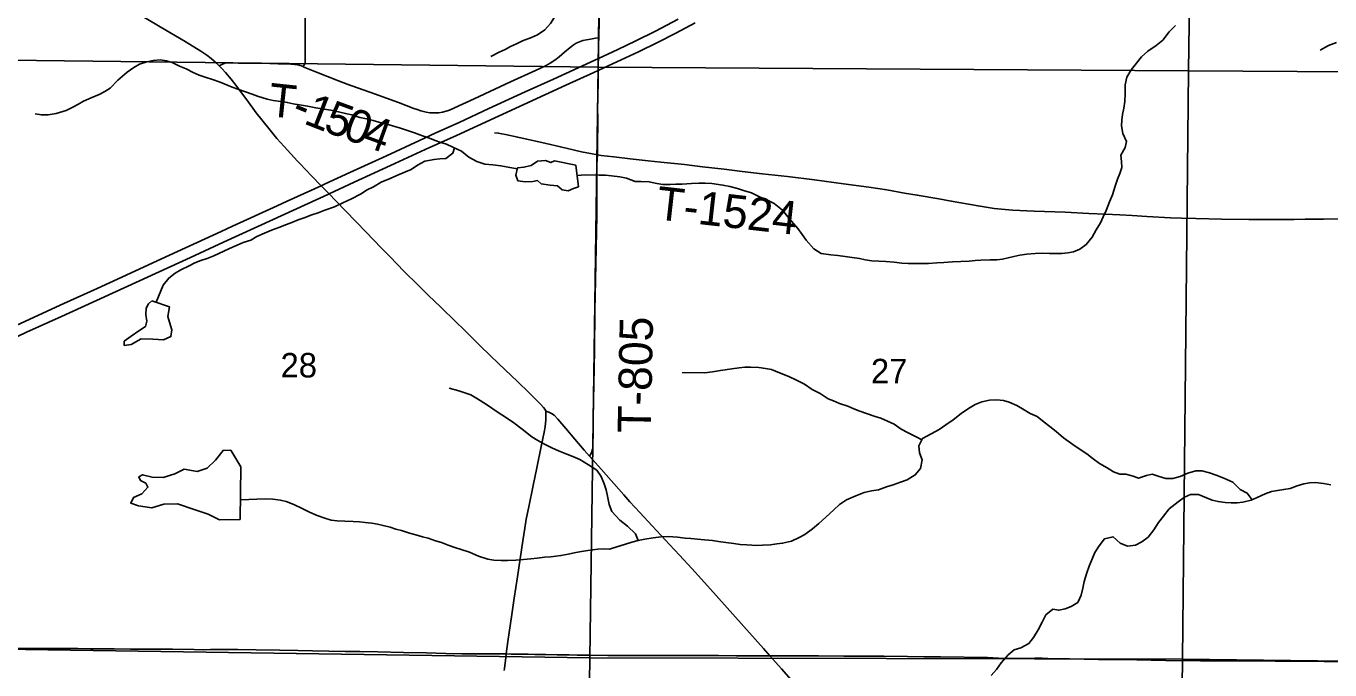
# Model space of a CAD drawing. Extents: x 1874609 to 2204689, y 815661 to 1281160.
# Drawn here: x 2024389 to 2036147, y 1030217 to 1036022 of the extents above; entities that cross this region are included whole.
import ezdxf

# ---------------------------------------------------------------- set-up
doc = ezdxf.new("R2010")
doc.units = 0
for name, color, linetype in [('GM_X_County_Road', 7, 'Continuous'), ('GM_X_Interstate_Route', 7, 'Continuous'), ('GM_X_Minor_Lake', 7, 'Continuous'), ('GM_X_Minor_River', 7, 'Continuous'), ('GM_X_Section', 7, 'Continuous'), ('GM_X_Section_Text', 7, 'Continuous'), ('GM_X_State_Route', 7, 'Continuous'), ('GM_X_Township_Road', 7, 'Continuous'), ('GM_X_Township_Road_Text', 7, 'Continuous')]:
    doc.layers.add(name, color=color, linetype=linetype)

msp = doc.modelspace()

# ---------------------------------------------------------------- linework, layer by layer
at = {"layer": 'GM_X_County_Road'}
for points in [[(2029076, 1032550), (2029103, 1032541), (2029128, 1032529), (2029150, 1032513), (2029183, 1032477), (2029256, 1032393), (2029337, 1032299), (2029422, 1032200), (2029471, 1032145)], [(2029471, 1032145), (2029574, 1032028), (2029781, 1031795), (2029835, 1031733), (2029923, 1031636), (2030034, 1031516), (2030112, 1031431), (2030190, 1031348), (2030281, 1031252), (2030392, 1031132), (2030481, 1031035), (2030612, 1030888), (2030788, 1030694), (2031038, 1030411), (2031096, 1030345)], [(2024315, 1030412), (2024447, 1030410), (2024578, 1030410), (2024643, 1030409), (2024725, 1030410), (2024790, 1030410), (2024856, 1030409), (2024971, 1030408), (2025085, 1030407), (2025184, 1030407), (2025331, 1030405), (2025479, 1030404), (2025709, 1030403), (2025906, 1030400), (2025987, 1030399), (2026053, 1030400), (2026299, 1030400), (2026463, 1030398), (2026676, 1030395), (2026840, 1030392), (2026971, 1030390), (2027266, 1030384), (2027398, 1030382), (2027562, 1030379), (2027793, 1030374), (2028000, 1030370), (2028175, 1030366), (2028320, 1030363), (2028381, 1030362), (2028430, 1030363), (2028451, 1030363), (2028502, 1030363), (2028560, 1030362), (2028641, 1030361), (2028684, 1030361), (2028719, 1030361)], [(2031096, 1030345), (2031200, 1030226), (2031439, 1029956), (2031537, 1029846), (2031701, 1029663), (2031790, 1029566), (2031791, 1029565)]]:
    msp.add_lwpolyline(points, dxfattribs=at)
at = {"layer": 'GM_X_Interstate_Route'}
for points in [[(2024268, 1033308), (2024731, 1033520), (2025029, 1033656), (2025253, 1033759), (2025610, 1033923), (2026147, 1034169), (2026252, 1034217), (2026654, 1034402), (2026743, 1034443), (2027051, 1034583), (2027087, 1034600), (2027310, 1034703), (2027639, 1034852), (2027937, 1034990), (2028085, 1035059), (2028294, 1035154), (2028562, 1035278), (2028891, 1035428), (2029144, 1035544), (2029517, 1035715), (2029550, 1035730), (2029726, 1035811), (2029889, 1035888), (2030065, 1035977), (2030269, 1036083)], [(2027110, 1034504), (2027122, 1034510), (2027348, 1034614), (2027676, 1034764), (2027989, 1034908), (2028272, 1035037), (2029256, 1035489), (2029510, 1035605), (2029549, 1035622), (2029600, 1035645), (2029912, 1035790), (2030089, 1035876), (2030249, 1035959), (2030423, 1036052)], [(2024191, 1033166), (2024203, 1033172), (2024230, 1033185), (2024394, 1033261), (2024708, 1033403), (2025871, 1033937), (2026170, 1034073), (2026617, 1034277), (2027109, 1034504), (2027110, 1034504)]]:
    msp.add_lwpolyline(points, dxfattribs=at)
at = {"layer": 'GM_X_Minor_Lake'}
for points in [[(2029347, 1034768), (2029153, 1034807), (2029121, 1034791), (2029072, 1034810), (2029002, 1034804), (2028944, 1034764), (2028878, 1034750), (2028820, 1034743), (2028805, 1034678), (2028825, 1034628), (2028891, 1034618), (2028960, 1034622), (2029000, 1034629), (2029034, 1034601), (2029116, 1034587), (2029182, 1034582), (2029222, 1034546), (2029278, 1034538), (2029326, 1034558), (2029372, 1034572)], [(2029372, 1034572), (2029347, 1034768)], [(2025524, 1033546), (2025492, 1033518), (2025471, 1033478), (2025469, 1033423), (2025479, 1033363), (2025465, 1033315), (2025406, 1033273), (2025336, 1033225), (2025274, 1033180), (2025274, 1033141), (2025336, 1033151), (2025428, 1033203), (2025533, 1033200), (2025629, 1033194), (2025695, 1033222), (2025703, 1033284), (2025681, 1033354), (2025668, 1033404), (2025682, 1033491)], [(2025682, 1033491), (2025524, 1033546)], [(2026326, 1032047), (2026235, 1032200), (2026166, 1032196), (2026098, 1032109), (2026021, 1032035), (2025931, 1032007), (2025815, 1032026), (2025731, 1031986), (2025626, 1031952), (2025526, 1031955), (2025440, 1031977), (2025406, 1031959), (2025420, 1031925), (2025468, 1031901), (2025488, 1031864), (2025433, 1031805), (2025357, 1031773), (2025333, 1031721), (2025403, 1031698), (2025523, 1031680), (2025631, 1031713), (2025754, 1031715), (2025904, 1031664), (2026032, 1031621), (2026134, 1031571), (2026321, 1031574)], [(2026321, 1031574), (2026326, 1032047)]]:
    msp.add_lwpolyline(points, dxfattribs=at)
at = {"layer": 'GM_X_Minor_River'}
for points in [[(2029373, 1036377), (2029303, 1036352), (2029252, 1036308), (2029214, 1036236), (2029186, 1036173), (2029155, 1036101), (2029117, 1036045), (2029067, 1035987), (2029000, 1035944), (2028948, 1035920), (2028866, 1035890), (2028812, 1035862), (2028759, 1035838), (2028709, 1035812), (2028655, 1035787), (2028579, 1035747)], [(2034754, 1036028), (2034696, 1035970), (2034639, 1035896), (2034579, 1035848), (2034504, 1035797), (2034448, 1035745), (2034404, 1035689), (2034354, 1035629), (2034315, 1035561), (2034299, 1035491), (2034301, 1035414), (2034298, 1035342), (2034288, 1035282), (2034276, 1035226), (2034270, 1035174), (2034268, 1035124), (2034279, 1035053), (2034311, 1034981), (2034299, 1034927), (2034261, 1034857), (2034268, 1034801), (2034270, 1034746), (2034252, 1034694), (2034230, 1034642), (2034211, 1034578), (2034187, 1034500), (2034159, 1034436), (2034130, 1034360), (2034102, 1034302), (2034078, 1034248), (2034040, 1034184), (2034003, 1034120), (2033949, 1034052), (2033893, 1034012), (2033834, 1033988), (2033784, 1033978), (2033728, 1033972), (2033674, 1033971), (2033618, 1033973), (2033552, 1033975), (2033488, 1033973), (2033415, 1033966), (2033351, 1033956), (2033297, 1033944), (2033245, 1033932), (2033195, 1033921), (2033143, 1033915), (2033084, 1033915), (2033000, 1033911), (2032948, 1033908), (2032894, 1033902)], [(2036207, 1035875), (2036134, 1035848), (2036058, 1035806)], [(2024471, 1035231), (2024527, 1035221), (2024588, 1035223), (2024660, 1035233), (2024752, 1035262), (2024804, 1035288), (2024855, 1035316), (2024907, 1035346), (2024975, 1035376), (2025047, 1035405), (2025098, 1035431), (2025148, 1035461), (2025218, 1035535), (2025301, 1035607), (2025361, 1035649), (2025411, 1035679), (2025477, 1035700), (2025536, 1035712), (2025598, 1035718), (2025656, 1035708), (2025706, 1035695), (2025774, 1035661), (2025832, 1035637), (2025896, 1035604), (2025950, 1035580), (2026012, 1035558), (2026070, 1035541), (2026140, 1035515), (2026248, 1035470), (2026300, 1035452), (2026368, 1035428), (2026427, 1035407), (2026477, 1035391), (2026563, 1035363), (2026617, 1035352), (2026685, 1035342), (2026745, 1035334), (2026799, 1035321), (2026855, 1035311), (2026927, 1035299), (2027001, 1035284), (2027078, 1035272), (2027136, 1035264), (2027206, 1035249), (2027270, 1035233), (2027326, 1035221), (2027398, 1035198), (2027460, 1035186), (2027518, 1035170), (2027570, 1035155), (2027642, 1035139), (2027767, 1035102), (2027893, 1035060), (2027963, 1035033), (2028027, 1035011), (2028079, 1034989), (2028129, 1034972), (2028179, 1034956), (2028239, 1034930), (2028317, 1034893), (2028383, 1034841), (2028455, 1034800), (2028527, 1034778), (2028599, 1034770), (2028669, 1034763), (2028818, 1034736)], [(2028252, 1034924), (2028237, 1034876), (2028174, 1034828), (2028120, 1034826), (2028068, 1034820), (2027986, 1034805), (2027918, 1034767), (2027861, 1034729), (2027811, 1034709), (2027733, 1034675), (2027671, 1034649), (2027592, 1034616), (2027522, 1034572), (2027466, 1034546), (2027404, 1034508), (2027323, 1034466), (2027245, 1034427), (2027169, 1034393), (2027084, 1034363), (2027024, 1034339), (2026966, 1034320), (2026898, 1034294), (2026843, 1034274), (2026787, 1034252), (2026737, 1034232), (2026667, 1034207), (2026601, 1034181), (2026540, 1034155), (2026470, 1034125), (2026416, 1034093), (2026346, 1034070), (2026293, 1034046), (2026223, 1034016), (2026173, 1033992), (2026082, 1033950), (2026022, 1033927), (2025966, 1033909), (2025910, 1033887), (2025860, 1033861), (2025785, 1033823), (2025733, 1033795), (2025675, 1033750), (2025624, 1033686), (2025562, 1033532)], [(2032894, 1033902), (2032820, 1033900), (2032742, 1033896), (2032665, 1033891), (2032603, 1033887), (2032527, 1033883), (2032473, 1033882), (2032345, 1033882), (2032287, 1033886), (2032216, 1033895), (2032142, 1033901), (2032078, 1033903), (2032016, 1033906), (2031956, 1033914), (2031904, 1033926), (2031840, 1033935), (2031774, 1033945), (2031709, 1033955), (2031647, 1033960), (2031559, 1033972), (2031493, 1034014), (2031425, 1034093), (2031387, 1034143), (2031350, 1034198), (2031270, 1034288), (2031210, 1034361), (2031134, 1034421), (2031058, 1034462), (2031008, 1034480), (2030930, 1034519), (2030860, 1034541), (2030804, 1034559), (2030735, 1034576), (2030673, 1034588), (2030573, 1034602), (2030513, 1034605), (2030455, 1034605), (2030391, 1034603), (2030305, 1034598), (2030248, 1034596), (2030196, 1034594), (2030130, 1034594), (2030078, 1034603), (2030008, 1034619), (2029932, 1034621), (2029882, 1034622), (2029804, 1034650), (2029743, 1034662), (2029667, 1034671), (2029615, 1034677), (2029557, 1034679), (2029431, 1034680), (2029359, 1034674)], [(2032467, 1032291), (2032423, 1032317), (2032345, 1032355), (2032281, 1032388), (2032217, 1032432), (2032157, 1032461), (2032097, 1032487), (2032047, 1032501), (2031967, 1032530), (2031907, 1032550), (2031855, 1032572), (2031799, 1032595), (2031723, 1032619), (2031671, 1032643), (2031621, 1032662), (2031551, 1032710), (2031477, 1032747), (2031409, 1032793), (2031337, 1032829), (2031267, 1032864), (2031182, 1032896), (2031112, 1032927), (2031058, 1032935), (2030996, 1032943), (2030922, 1032948), (2030870, 1032948), (2030820, 1032942), (2030752, 1032932), (2030651, 1032917), (2030579, 1032905), (2030511, 1032897), (2030306, 1032898)], [(2029908, 1031383), (2029884, 1031444), (2029812, 1031512), (2029742, 1031567), (2029670, 1031645), (2029647, 1031709), (2029633, 1031784), (2029621, 1031842), (2029601, 1031896), (2029575, 1031961), (2029536, 1032017), (2029462, 1032067), (2029384, 1032114), (2029319, 1032142), (2029265, 1032163), (2029189, 1032193), (2029131, 1032219), (2029057, 1032256), (2029003, 1032286), (2028949, 1032318), (2028863, 1032387), (2028789, 1032446), (2028711, 1032496), (2028645, 1032537), (2028541, 1032609), (2028459, 1032662), (2028401, 1032696), (2028345, 1032714), (2028291, 1032733), (2028205, 1032757)], [(2035445, 1031752), (2035402, 1031812), (2035338, 1031845), (2035270, 1031911), (2035190, 1031946), (2035120, 1031974), (2035062, 1031994), (2034992, 1032013), (2034938, 1032011), (2034866, 1031991), (2034795, 1031961), (2034731, 1031942), (2034667, 1031944), (2034607, 1031962), (2034545, 1031983), (2034493, 1031971), (2034422, 1031945), (2034372, 1031965), (2034306, 1031982), (2034252, 1031982), (2034194, 1032002), (2034138, 1032038), (2034068, 1032079), (2034012, 1032121), (2033956, 1032166), (2033896, 1032206), (2033828, 1032251), (2033744, 1032311), (2033678, 1032366), (2033622, 1032412), (2033570, 1032452), (2033506, 1032501), (2033444, 1032529), (2033376, 1032572), (2033324, 1032602), (2033254, 1032632), (2033202, 1032647), (2033144, 1032653), (2033078, 1032649), (2033008, 1032633), (2032947, 1032610), (2032887, 1032574), (2032823, 1032528), (2032749, 1032472), (2032682, 1032428), (2032622, 1032384), (2032552, 1032347), (2032473, 1032305), (2032441, 1032239), (2032447, 1032176), (2032469, 1032110), (2032456, 1032034), (2032408, 1031976), (2032334, 1031932), (2032275, 1031910), (2032207, 1031885), (2032149, 1031869), (2032077, 1031841), (2032013, 1031831), (2031946, 1031816), (2031872, 1031786), (2031788, 1031752), (2031725, 1031710), (2031673, 1031662), (2031601, 1031594), (2031538, 1031537), (2031482, 1031489), (2031412, 1031439), (2031362, 1031411), (2031291, 1031379), (2031211, 1031359), (2031159, 1031354), (2031101, 1031344), (2031031, 1031342), (2030978, 1031340), (2030888, 1031345), (2030830, 1031347), (2030772, 1031357), (2030700, 1031366), (2030634, 1031376), (2030580, 1031384), (2030507, 1031389), (2030443, 1031395), (2030383, 1031401), (2030333, 1031405), (2030263, 1031414), (2030179, 1031420), (2030115, 1031418), (2030045, 1031409), (2029968, 1031395), (2029910, 1031383), (2029852, 1031368), (2029786, 1031348), (2029715, 1031326), (2029649, 1031306), (2029599, 1031308), (2029545, 1031305), (2029455, 1031293), (2029399, 1031285), (2029348, 1031277), (2029278, 1031262)], [(2033141, 1030221), (2033182, 1030281), (2033244, 1030353), (2033300, 1030397), (2033359, 1030417), (2033431, 1030457), (2033475, 1030511), (2033517, 1030579), (2033552, 1030649), (2033586, 1030713), (2033648, 1030765), (2033701, 1030756), (2033759, 1030768), (2033813, 1030788), (2033873, 1030826), (2033905, 1030892), (2033918, 1030954), (2033932, 1031014), (2033954, 1031094), (2033977, 1031154), (2034007, 1031225), (2034027, 1031275), (2034067, 1031337), (2034114, 1031399), (2034192, 1031418), (2034256, 1031360), (2034322, 1031333), (2034394, 1031341), (2034450, 1031373), (2034507, 1031415), (2034559, 1031479), (2034601, 1031547), (2034646, 1031603), (2034698, 1031669), (2034779, 1031733), (2034835, 1031775), (2034891, 1031798), (2034961, 1031798), (2035035, 1031770), (2035085, 1031747), (2035139, 1031735), (2035203, 1031727), (2035256, 1031723), (2035310, 1031724), (2035362, 1031730), (2035436, 1031748), (2035490, 1031772), (2035563, 1031805), (2035619, 1031825), (2035675, 1031835), (2035731, 1031845), (2035787, 1031853), (2035853, 1031876), (2035912, 1031896), (2035964, 1031904), (2036018, 1031908), (2036090, 1031897), (2036154, 1031885)], [(2029278, 1031262), (2029212, 1031248), (2029122, 1031236), (2029064, 1031233), (2028997, 1031225), (2028941, 1031219), (2028875, 1031213), (2028805, 1031208), (2028731, 1031204), (2028673, 1031204), (2028606, 1031207), (2028552, 1031217), (2028470, 1031243), (2028388, 1031278), (2028314, 1031304), (2028256, 1031322), (2028196, 1031343), (2028136, 1031365), (2028082, 1031381), (2028016, 1031404), (2027964, 1031418), (2027904, 1031434), (2027848, 1031451), (2027776, 1031473), (2027723, 1031487), (2027671, 1031504), (2027609, 1031518), (2027557, 1031532), (2027507, 1031540), (2027447, 1031547), (2027395, 1031551), (2027339, 1031555), (2027265, 1031558), (2027194, 1031562), (2027140, 1031568), (2027084, 1031587), (2027014, 1031611), (2026944, 1031639), (2026878, 1031674), (2026804, 1031708), (2026734, 1031735), (2026684, 1031747), (2026614, 1031757), (2026546, 1031759), (2026323, 1031751)], [(2033093, 1030167), (2033141, 1030221)]]:
    msp.add_lwpolyline(points, dxfattribs=at)
at = {"layer": 'GM_X_Section'}
for points in [[(2024307, 1041051), (2029614, 1041008), (2029549, 1035653), (2024232, 1035714)], [(2029614, 1041008), (2033958, 1040951), (2034947, 1040891), (2034872, 1035620), (2029549, 1035653)], [(2040294, 1040893), (2040263, 1035584), (2034872, 1035620), (2034947, 1040891)], [(2024232, 1035714), (2029549, 1035653), (2029474, 1030326), (2024181, 1030403)], [(2029549, 1035653), (2034872, 1035620), (2034817, 1030315), (2029474, 1030326)], [(2034872, 1035620), (2040263, 1035584), (2040172, 1030247), (2034817, 1030315)], [(2029474, 1030326), (2029401, 1025035), (2025081, 1025088), (2024088, 1025128), (2024181, 1030403)], [(2029474, 1030326), (2034817, 1030315), (2034750, 1024982), (2030074, 1025026), (2029401, 1025035)], [(2034817, 1030315), (2040172, 1030247), (2040056, 1024942), (2035188, 1024961), (2034750, 1024982)]]:
    msp.add_lwpolyline(points, close=True, dxfattribs=at)
at = {"layer": 'GM_X_State_Route'}
for points in [[(2026380, 1035356), (2026368, 1035372), (2026291, 1035478), (2026240, 1035543), (2026187, 1035605), (2026154, 1035641), (2026131, 1035663), (2026107, 1035687), (2026058, 1035730), (2026019, 1035760), (2025965, 1035797), (2025825, 1035882), (2025599, 1036016), (2025472, 1036091), (2025359, 1036156)], [(2026838, 1034804), (2026716, 1034935), (2026650, 1035009), (2026577, 1035098), (2026465, 1035240), (2026380, 1035356)], [(2027117, 1034516), (2027051, 1034583), (2026964, 1034673), (2026861, 1034779), (2026838, 1034804)], [(2027183, 1034447), (2027122, 1034510), (2027117, 1034516)], [(2028059, 1033555), (2028031, 1033582), (2027926, 1033685), (2027797, 1033812), (2027671, 1033941), (2027590, 1034022), (2027455, 1034165), (2027364, 1034260), (2027183, 1034447)], [(2028701, 1030213), (2028702, 1030231), (2028715, 1030328), (2028719, 1030361), (2028735, 1030474), (2028771, 1030717), (2028792, 1030863), (2028820, 1031057), (2028845, 1031219), (2028856, 1031300), (2028868, 1031381), (2028886, 1031494), (2028900, 1031575), (2028922, 1031687), (2028961, 1031880), (2028994, 1032040), (2029035, 1032232), (2029062, 1032360), (2029069, 1032408), (2029075, 1032473), (2029077, 1032500), (2029077, 1032515), (2029077, 1032530), (2029076, 1032550), (2029069, 1032566), (2029056, 1032583), (2029030, 1032611), (2028996, 1032647), (2028926, 1032715), (2028820, 1032818), (2028653, 1032976), (2028570, 1033055), (2028488, 1033136), (2028350, 1033275), (2028255, 1033365), (2028137, 1033479), (2028059, 1033555)]]:
    msp.add_lwpolyline(points, dxfattribs=at)
at = {"layer": 'GM_X_Township_Road'}
for points in [[(2026889, 1035656), (2026898, 1035672), (2026905, 1035685), (2026906, 1035700), (2026906, 1035716), (2026905, 1035831), (2026908, 1036644), (2026912, 1036820), (2026912, 1036837), (2026914, 1036952), (2026914, 1037379), (2026915, 1037510), (2026916, 1037592), (2026913, 1037697), (2026909, 1037839), (2026916, 1038220)], [(2029553, 1035916), (2029556, 1036076), (2029561, 1036453), (2029563, 1036598)], [(2027887, 1035280), (2027917, 1035269), (2027949, 1035259), (2027997, 1035247), (2028030, 1035241), (2028062, 1035239), (2028095, 1035239), (2028111, 1035241), (2028144, 1035246), (2028176, 1035255), (2028207, 1035265), (2028252, 1035284), (2028431, 1035367), (2028759, 1035519), (2028983, 1035621), (2029072, 1035664), (2029115, 1035688), (2029157, 1035715), (2029196, 1035745), (2029246, 1035788), (2029295, 1035830), (2029322, 1035850), (2029350, 1035867), (2029380, 1035881), (2029411, 1035891), (2029443, 1035898), (2029480, 1035905), (2029524, 1035912), (2029553, 1035916)], [(2029543, 1034976), (2029545, 1035137), (2029545, 1035206), (2029543, 1035258), (2029547, 1035519), (2029549, 1035622), (2029549, 1035683), (2029550, 1035730), (2029552, 1035863), (2029553, 1035916)], [(2026131, 1035663), (2026154, 1035677), (2026174, 1035685), (2026190, 1035690), (2026203, 1035692), (2026301, 1035689), (2026366, 1035689), (2026513, 1035687), (2026661, 1035683), (2026776, 1035680), (2026809, 1035677), (2026841, 1035672), (2026873, 1035663), (2026888, 1035657), (2026889, 1035656)], [(2026889, 1035656), (2026918, 1035643), (2027009, 1035607), (2027207, 1035528), (2027284, 1035499), (2027532, 1035411), (2027749, 1035333), (2027887, 1035280)], [(2028614, 1035061), (2028647, 1035058), (2028711, 1035046), (2028823, 1035020), (2029080, 1034962), (2029207, 1034932), (2029399, 1034888), (2029479, 1034872), (2029543, 1034860)], [(2029543, 1034860), (2029543, 1034918), (2029543, 1034976)], [(2029471, 1032145), (2029487, 1032176), (2029497, 1032207), (2029500, 1032221), (2029501, 1032238), (2029503, 1032367), (2029503, 1032505), (2029506, 1032650), (2029512, 1032940), (2029515, 1033100), (2029519, 1033454), (2029525, 1033733), (2029535, 1034311), (2029535, 1034402), (2029537, 1034471), (2029536, 1034615), (2029537, 1034693), (2029537, 1034780), (2029543, 1034860)], [(2029543, 1034860), (2029576, 1034856), (2029690, 1034842), (2029836, 1034824), (2030000, 1034807), (2030114, 1034795), (2030326, 1034773), (2030489, 1034754), (2030684, 1034732), (2030847, 1034712), (2031027, 1034691), (2031255, 1034667), (2031500, 1034636), (2031760, 1034601), (2031988, 1034570), (2032150, 1034545), (2032311, 1034517), (2032425, 1034498), (2032619, 1034464), (2032732, 1034444), (2032974, 1034401), (2033120, 1034378), (2033185, 1034370), (2033283, 1034363), (2033480, 1034354), (2033759, 1034343), (2033972, 1034332), (2034119, 1034326), (2034251, 1034320), (2034365, 1034313), (2034496, 1034306), (2034709, 1034294), (2034808, 1034290), (2034939, 1034287), (2035169, 1034282), (2035415, 1034279), (2035694, 1034278), (2035825, 1034279), (2035924, 1034280), (2036088, 1034282), (2036235, 1034283)], [(2028719, 1030361), (2028763, 1030360), (2028797, 1030360), (2028845, 1030359), (2028916, 1030358), (2028977, 1030357), (2028993, 1030356), (2029009, 1030356), (2029026, 1030355), (2029075, 1030355), (2029179, 1030354), (2029288, 1030352), (2029359, 1030351), (2029473, 1030349), (2029636, 1030348), (2029788, 1030348), (2029941, 1030348), (2030115, 1030347), (2030270, 1030347), (2030632, 1030346), (2030796, 1030345), (2030944, 1030344), (2031096, 1030345)], [(2031096, 1030345), (2031124, 1030345), (2031272, 1030345), (2031403, 1030345), (2031534, 1030343), (2031764, 1030342), (2031944, 1030342), (2032125, 1030340), (2032338, 1030337), (2032486, 1030336), (2032634, 1030334), (2033060, 1030328), (2033159, 1030324), (2033274, 1030321), (2033356, 1030321), (2033487, 1030322), (2033552, 1030322), (2033602, 1030319), (2033798, 1030316), (2033930, 1030314), (2034061, 1030312), (2034274, 1030311), (2034668, 1030303), (2034980, 1030299), (2035161, 1030298), (2035374, 1030298), (2035653, 1030295), (2035834, 1030295), (2036096, 1030293), (2036326, 1030294)]]:
    msp.add_lwpolyline(points, dxfattribs=at)

# ---------------------------------------------------------------- texts
at = {"layer": 'GM_X_Section_Text'}
for s, p in [('28', (2026684, 1032854)), ('27', (2032008, 1032801))]:
    msp.add_text(s, height=221, rotation=0, dxfattribs=at).set_placement(p)
at = {"layer": 'GM_X_Township_Road_Text'}
for s, rotation, p in [('T', 353.946, (2026565, 1035212)), ('-', 338.0738, (2026767, 1035194)), ('1', 338.5271, (2026882, 1035147)), ('5', 339.7924, (2027060, 1035078)), ('0', 340.0521, (2027233, 1035014)), ('4', 340.0529, (2027405, 1034951)), ('T-1524', 353.5894, (2030063, 1034281)), ('T-805', 88.8927, (2030023, 1032352))]:
    msp.add_text(s, height=300, rotation=rotation, dxfattribs=at).set_placement(p)

doc.saveas('drawing.dxf')
